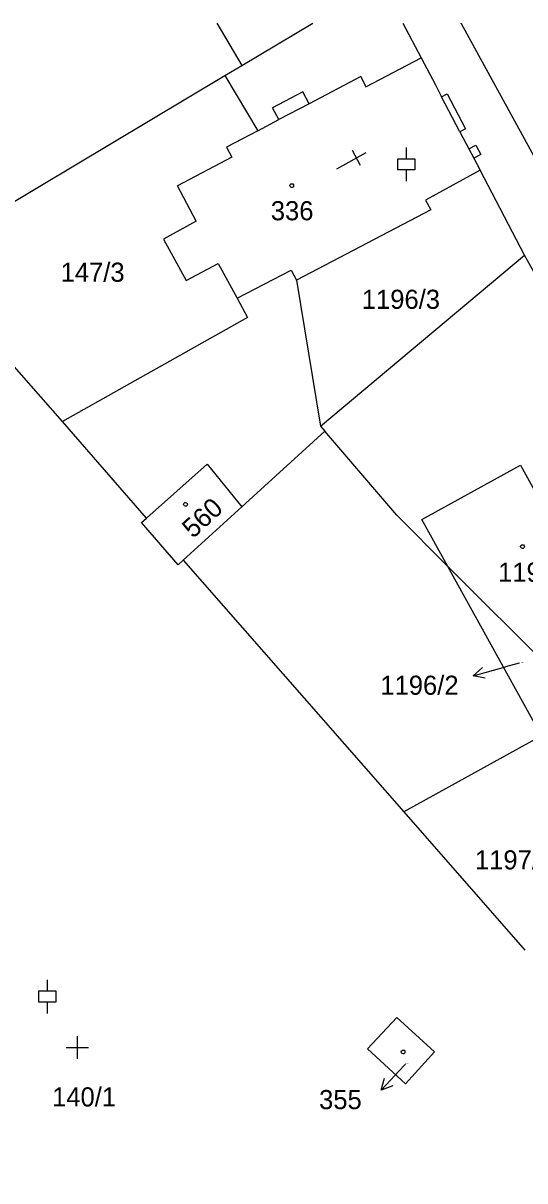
# Model space of a CAD drawing. Extents: x -777309 to -774195, y -1144706 to -1143600.
# Drawn here: x -774578.2 to -774533.6, y -1144303 to -1144200 of the extents above; entities that cross this region are included whole.
import ezdxf

# ---------------------------------------------------------------- set-up
doc = ezdxf.new("R2010")
doc.units = 0
for name, color, linetype in [('1', 7, 'Continuous'), ('12', 7, 'Continuous'), ('2', 7, 'Continuous'), ('3', 7, 'Continuous'), ('4', 7, 'Continuous'), ('5', 7, 'Continuous'), ('7', 7, 'Continuous')]:
    doc.layers.add(name, color=color, linetype=linetype)

msp = doc.modelspace()

# ---------------------------------------------------------------- linework, layer by layer
at = {"layer": '1'}
for p, q in [((-774558.8, -1144203.77), (-774552.48, -1144200)), ((-774544.46, -1144200), (-774542.85, -1144203.08)), ((-774539.29, -1144200.03), (-774539.3, -1144200)), ((-774539.29, -1144200.03), (-774483.01, -1144303.01)), ((-774542.85, -1144203.08), (-774541.58, -1144205.5)), ((-774560.3, -1144204.67), (-774558.8, -1144203.77)), ((-774582.97, -1144218.23), (-774560.3, -1144204.67)), ((-774560.3, -1144204.67), (-774557.37, -1144209.57)), ((-774541.58, -1144205.5), (-774541.02, -1144206.56)), ((-774539.4, -1144209.66), (-774541.02, -1144206.56)), ((-774557.37, -1144209.57), (-774560.14, -1144211.03)), ((-774539.4, -1144209.66), (-774538.6, -1144211.18)), ((-774560.14, -1144211.03), (-774559.68, -1144211.93)), ((-774538.6, -1144211.18), (-774538.16, -1144212.02)), ((-774559.68, -1144211.93), (-774564.5, -1144214.47)), ((-774538.16, -1144212.02), (-774537.61, -1144213.07)), ((-774537.61, -1144213.07), (-774542.47, -1144215.74)), ((-774533.64, -1144220.64), (-774537.61, -1144213.07)), ((-774562.86, -1144217.62), (-774564.5, -1144214.47)), ((-774542.47, -1144215.74), (-774541.99, -1144216.62)), ((-774541.99, -1144216.62), (-774553.93, -1144222.88)), ((-774562.86, -1144217.62), (-774565.74, -1144219.22)), ((-774565.74, -1144219.22), (-774563.74, -1144222.89)), ((-774551.8, -1144235.86), (-774533.64, -1144220.64)), ((-774528.56, -1144229.85), (-774533.64, -1144220.64)), ((-774563.74, -1144222.89), (-774560.88, -1144221.4)), ((-774560.88, -1144221.4), (-774559.2, -1144224.48)), ((-774553.93, -1144222.88), (-774551.8, -1144235.86)), ((-774559.2, -1144224.48), (-774558.27, -1144226.19)), ((-774558.27, -1144226.19), (-774574.73, -1144235.44)), ((-774574.73, -1144235.44), (-774581.7, -1144227.54)), ((-774567.27, -1144244.04), (-774574.73, -1144235.44)), ((-774551.8, -1144235.86), (-774551.41, -1144236.31)), ((-774551.41, -1144236.31), (-774558.8, -1144243.04)), ((-774545.02, -1144243.79), (-774551.41, -1144236.31)), ((-774567.27, -1144244.04), (-774561.87, -1144239.25)), ((-774561.87, -1144239.25), (-774558.8, -1144243.04)), ((-774558.8, -1144243.04), (-774564, -1144247.79)), ((-774567.72, -1144244.43), (-774567.27, -1144244.04)), ((-774540.47, -1144248.34), (-774545.02, -1144243.79)), ((-774564.45, -1144248.19), (-774567.72, -1144244.43)), ((-774564, -1144247.79), (-774564.45, -1144248.19)), ((-774564, -1144247.79), (-774544.37, -1144270.17)), ((-774528.46, -1144260.33), (-774540.47, -1144248.34)), ((-774532.14, -1144263.41), (-774544.37, -1144270.17)), ((-774544.37, -1144270.17), (-774533.61, -1144282.48)), ((-774547.62, -1144291.26), (-774545.01, -1144288.47)), ((-774541.66, -1144291.52), (-774545.01, -1144288.47)), ((-774547.62, -1144291.26), (-774544.24, -1144294.39)), ((-774541.66, -1144291.52), (-774544.24, -1144294.39))]:
    msp.add_line(p, q, dxfattribs=at)
at = {"layer": '12'}
for p, q in [((-774561.02, -1144200), (-774558.8, -1144203.77)), ((-774558.8, -1144203.77), (-774552.48, -1144200)), ((-774547.75, -1144205.67), (-774542.85, -1144203.08)), ((-774542.85, -1144203.08), (-774541.58, -1144205.5)), ((-774548.22, -1144204.75), (-774552.81, -1144207.17)), ((-774548.22, -1144204.75), (-774547.75, -1144205.67)), ((-774541.58, -1144205.5), (-774541.02, -1144206.56)), ((-774552.81, -1144207.17), (-774555.49, -1144208.58)), ((-774539.4, -1144209.66), (-774541.02, -1144206.56)), ((-774557.37, -1144209.57), (-774555.49, -1144208.58)), ((-774557.37, -1144209.57), (-774560.14, -1144211.03)), ((-774539.4, -1144209.66), (-774538.6, -1144211.18)), ((-774560.14, -1144211.03), (-774559.68, -1144211.93)), ((-774538.6, -1144211.18), (-774538.16, -1144212.02)), ((-774559.68, -1144211.93), (-774564.5, -1144214.47)), ((-774538.16, -1144212.02), (-774537.61, -1144213.07)), ((-774537.61, -1144213.07), (-774542.47, -1144215.74)), ((-774562.86, -1144217.62), (-774564.5, -1144214.47)), ((-774542.47, -1144215.74), (-774541.99, -1144216.62)), ((-774541.99, -1144216.62), (-774553.93, -1144222.88)), ((-774562.86, -1144217.62), (-774565.74, -1144219.22)), ((-774565.74, -1144219.22), (-774563.74, -1144222.89)), ((-774563.74, -1144222.89), (-774560.88, -1144221.4)), ((-774560.88, -1144221.4), (-774559.2, -1144224.48)), ((-774559.2, -1144224.48), (-774554.41, -1144221.99)), ((-774554.41, -1144221.99), (-774553.93, -1144222.88)), ((-774567.27, -1144244.04), (-774561.87, -1144239.25)), ((-774561.87, -1144239.25), (-774558.8, -1144243.04)), ((-774542.77, -1144244.17), (-774534.02, -1144239.34)), ((-774534.02, -1144239.34), (-774523.4, -1144258.58)), ((-774558.8, -1144243.04), (-774564, -1144247.79)), ((-774567.72, -1144244.43), (-774567.27, -1144244.04)), ((-774540.47, -1144248.34), (-774542.77, -1144244.17)), ((-774564.45, -1144248.19), (-774567.72, -1144244.43)), ((-774564, -1144247.79), (-774564.45, -1144248.19)), ((-774532.14, -1144263.41), (-774540.47, -1144248.34)), ((-774547.62, -1144291.26), (-774545.01, -1144288.47)), ((-774541.66, -1144291.52), (-774545.01, -1144288.47)), ((-774547.62, -1144291.26), (-774544.24, -1144294.39)), ((-774541.66, -1144291.52), (-774544.24, -1144294.39))]:
    msp.add_line(p, q, dxfattribs=at)
at = {"layer": '3'}
for p, q in [((-774544.16, -1144212.06), (-774544.16, -1144211.06)), ((-774576.08, -1144286.11), (-774576.08, -1144285.11)), ((-774573.41, -1144292.15), (-774573.41, -1144290.15)), ((-774574.41, -1144291.15), (-774572.41, -1144291.15))]:
    msp.add_line(p, q, dxfattribs=at)
for points in [[(-774544.16, -1144214.06), (-774544.16, -1144213.06), (-774544.91, -1144213.06), (-774544.91, -1144212.06), (-774544.16, -1144212.06), (-774543.41, -1144212.06), (-774543.41, -1144213.06), (-774544.16, -1144213.06)], [(-774576.08, -1144288.11), (-774576.08, -1144287.11), (-774576.83, -1144287.11), (-774576.83, -1144286.11), (-774576.08, -1144286.11), (-774575.33, -1144286.11), (-774575.33, -1144287.11), (-774576.08, -1144287.11)]]:
    msp.add_lwpolyline(points, dxfattribs=at)
at = {"layer": '4'}
for p, q in [((-774561.02, -1144200), (-774558.8, -1144203.77)), ((-774547.75, -1144205.67), (-774542.85, -1144203.08)), ((-774548.22, -1144204.75), (-774552.81, -1144207.17)), ((-774548.22, -1144204.75), (-774547.75, -1144205.67)), ((-774553.37, -1144206.11), (-774556.05, -1144207.52)), ((-774552.81, -1144207.17), (-774553.37, -1144206.11)), ((-774552.81, -1144207.17), (-774555.49, -1144208.58)), ((-774541.02, -1144206.56), (-774540.54, -1144206.3)), ((-774540.54, -1144206.3), (-774538.91, -1144209.4)), ((-774555.49, -1144208.58), (-774556.05, -1144207.52)), ((-774557.37, -1144209.57), (-774555.49, -1144208.58)), ((-774538.91, -1144209.4), (-774539.4, -1144209.66)), ((-774538.6, -1144211.18), (-774537.98, -1144210.86)), ((-774537.98, -1144210.86), (-774537.54, -1144211.7)), ((-774537.54, -1144211.7), (-774538.16, -1144212.02)), ((-774559.2, -1144224.48), (-774554.41, -1144221.99)), ((-774554.41, -1144221.99), (-774553.93, -1144222.88)), ((-774542.77, -1144244.17), (-774534.02, -1144239.34)), ((-774534.02, -1144239.34), (-774523.4, -1144258.58)), ((-774540.47, -1144248.34), (-774542.77, -1144244.17)), ((-774532.14, -1144263.41), (-774540.47, -1144248.34))]:
    msp.add_line(p, q, dxfattribs=at)
at = {"layer": '5'}
for p, q in [((-774548.24, -1144212.66), (-774548.96, -1144211.34)), ((-774550.35, -1144212.96), (-774547.72, -1144211.52))]:
    msp.add_line(p, q, dxfattribs=at)
for points in [[(-774554.35, -1144214.29), (-774554.25, -1144214.31), (-774554.2, -1144214.4), (-774554.18, -1144214.46), (-774554.2, -1144214.55), (-774554.28, -1144214.62), (-774554.35, -1144214.63), (-774554.44, -1144214.6), (-774554.5, -1144214.54), (-774554.52, -1144214.46), (-774554.5, -1144214.37), (-774554.42, -1144214.3)], [(-774563.79, -1144242.65), (-774563.69, -1144242.67), (-774563.64, -1144242.76), (-774563.62, -1144242.82), (-774563.64, -1144242.91), (-774563.72, -1144242.98), (-774563.79, -1144242.99), (-774563.88, -1144242.96), (-774563.94, -1144242.9), (-774563.96, -1144242.82), (-774563.94, -1144242.73), (-774563.86, -1144242.66)], [(-774533.83, -1144246.41), (-774533.73, -1144246.43), (-774533.68, -1144246.52), (-774533.66, -1144246.58), (-774533.68, -1144246.67), (-774533.76, -1144246.74), (-774533.83, -1144246.75), (-774533.92, -1144246.72), (-774533.98, -1144246.66), (-774534, -1144246.58), (-774533.98, -1144246.49), (-774533.9, -1144246.42)], [(-774544.44, -1144291.37), (-774544.34, -1144291.39), (-774544.29, -1144291.48), (-774544.27, -1144291.54), (-774544.29, -1144291.63), (-774544.37, -1144291.7), (-774544.44, -1144291.71), (-774544.53, -1144291.68), (-774544.59, -1144291.62), (-774544.61, -1144291.54), (-774544.59, -1144291.45), (-774544.51, -1144291.38)]]:
    msp.add_lwpolyline(points, close=True, dxfattribs=at)
at = {"layer": '7'}
for p, q in [((-774538.23, -1144258.06), (-774535.34, -1144257.27)), ((-774534.14, -1144256.94), (-774535.34, -1144257.27)), ((-774546.41, -1144294.93), (-774544.35, -1144292.75)), ((-774544.23, -1144292.62), (-774544.35, -1144292.75))]:
    msp.add_line(p, q, dxfattribs=at)
for points in [[(-774537.14, -1144258.28), (-774538.23, -1144258.06), (-774537.4, -1144257.32)], [(-774545.36, -1144294.55), (-774546.41, -1144294.93), (-774546.09, -1144293.86)]]:
    msp.add_lwpolyline(points, dxfattribs=at)

# ---------------------------------------------------------------- texts
at = {"layer": '2'}
for s, height, p in [('336', 1.7, (-774556.21, -1144217.54)), ('147/3', 1.7, (-774574.9, -1144223.01)), ('1196/3', 1.7, (-774548.12, -1144225.42)), ('1196/1', 1.7, (-774536, -1144249.7)), ('1196/2', 0.1, (-774534.12, -1144256.94)), ('355', 0.1, (-774544.22, -1144292.62)), ('140/1', 1.7, (-774575.66, -1144296.39))]:
    msp.add_text(s, height=height, dxfattribs=at).set_placement(p)
msp.add_text('560', height=1.7, rotation=42.5708, dxfattribs=at).set_placement((-774563.13, -1144245.91))
at = {"layer": '7'}
for s, p in [('1196/2', (-774546.47, -1144259.76)), ('1197/2', (-774538.06, -1144275.3)), ('355', (-774551.92, -1144296.63))]:
    msp.add_text(s, height=1.7, dxfattribs=at).set_placement(p)

doc.saveas('drawing.dxf')
